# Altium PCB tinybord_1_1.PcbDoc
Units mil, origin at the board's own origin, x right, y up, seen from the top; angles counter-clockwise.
Board outline 1400 x 1800 mil, 2 copper layers (Top Layer, Bottom Layer), stack 21 mil thick; 59 components, 54 nets, 273 pads, 164 vias.
Unrouted connection lines stored in the file: 122.
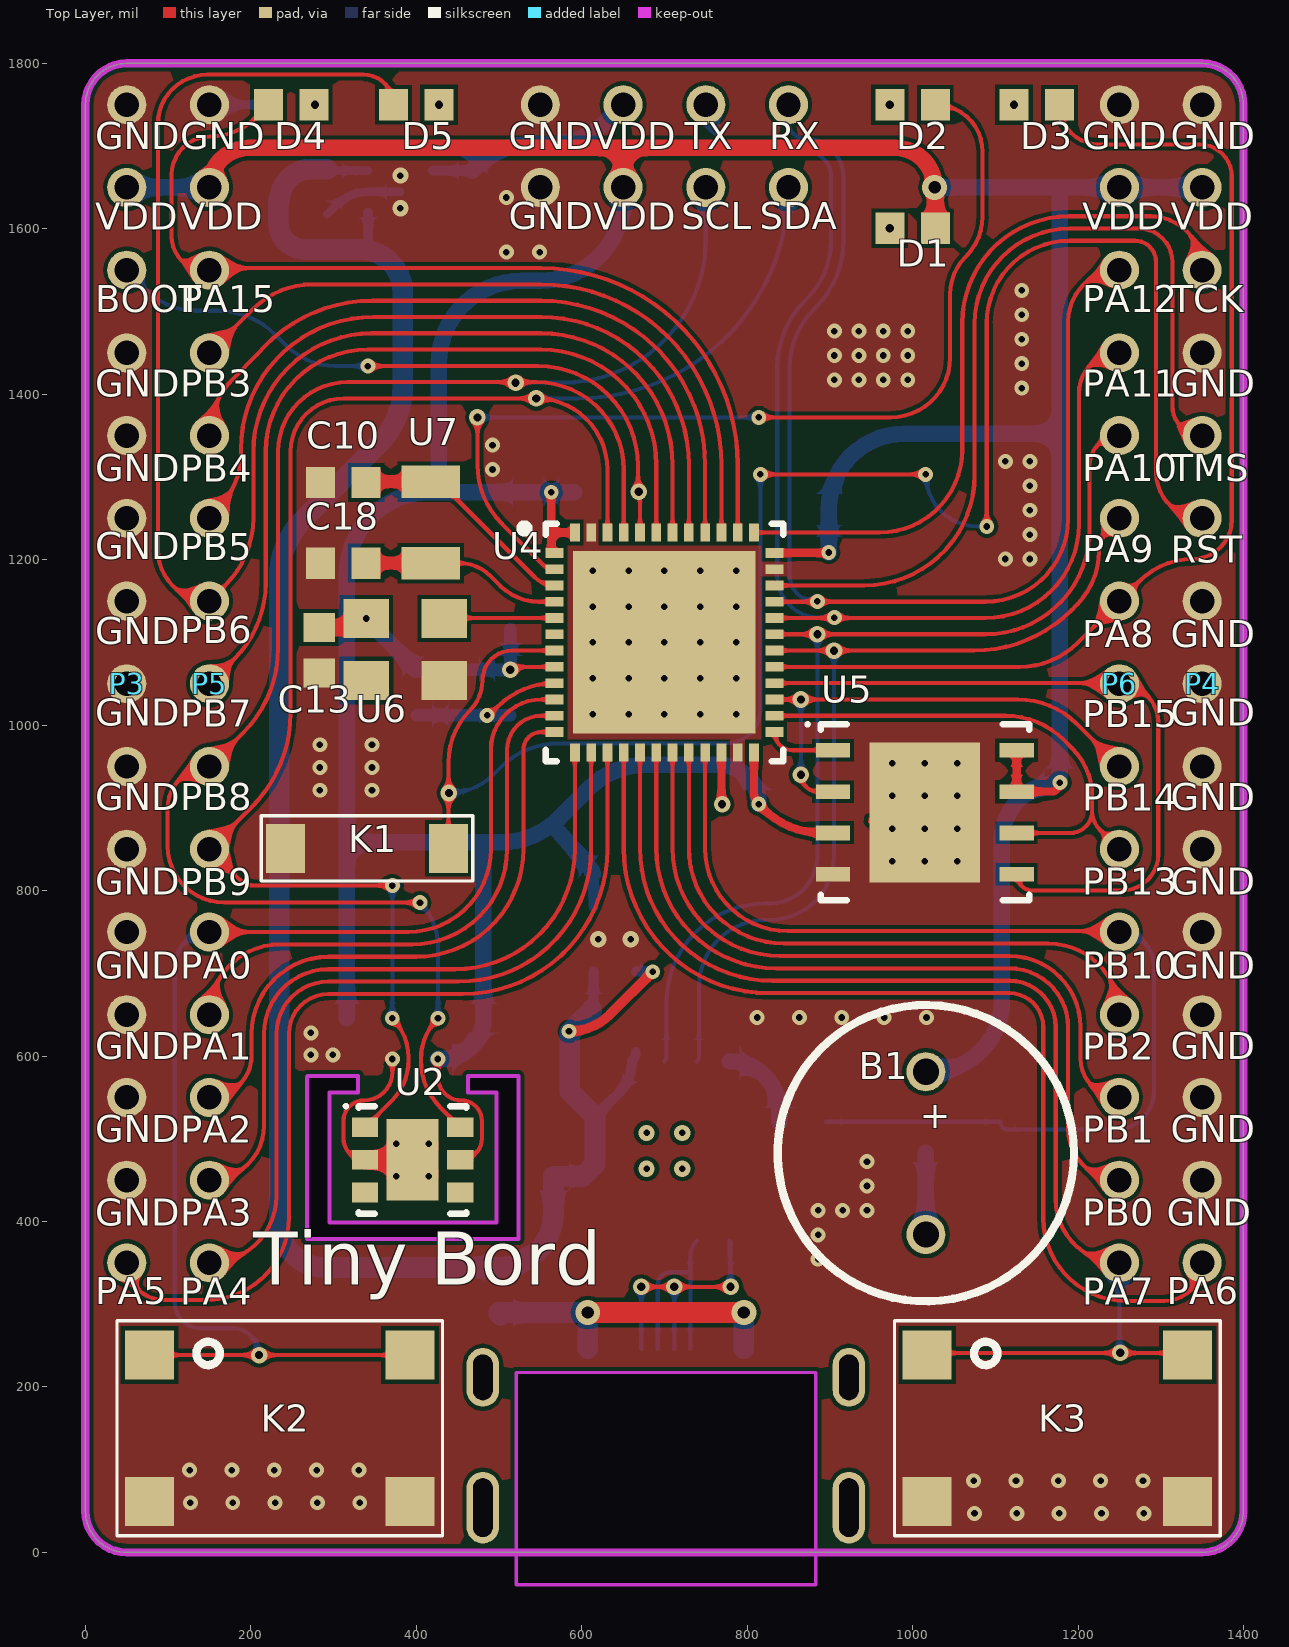
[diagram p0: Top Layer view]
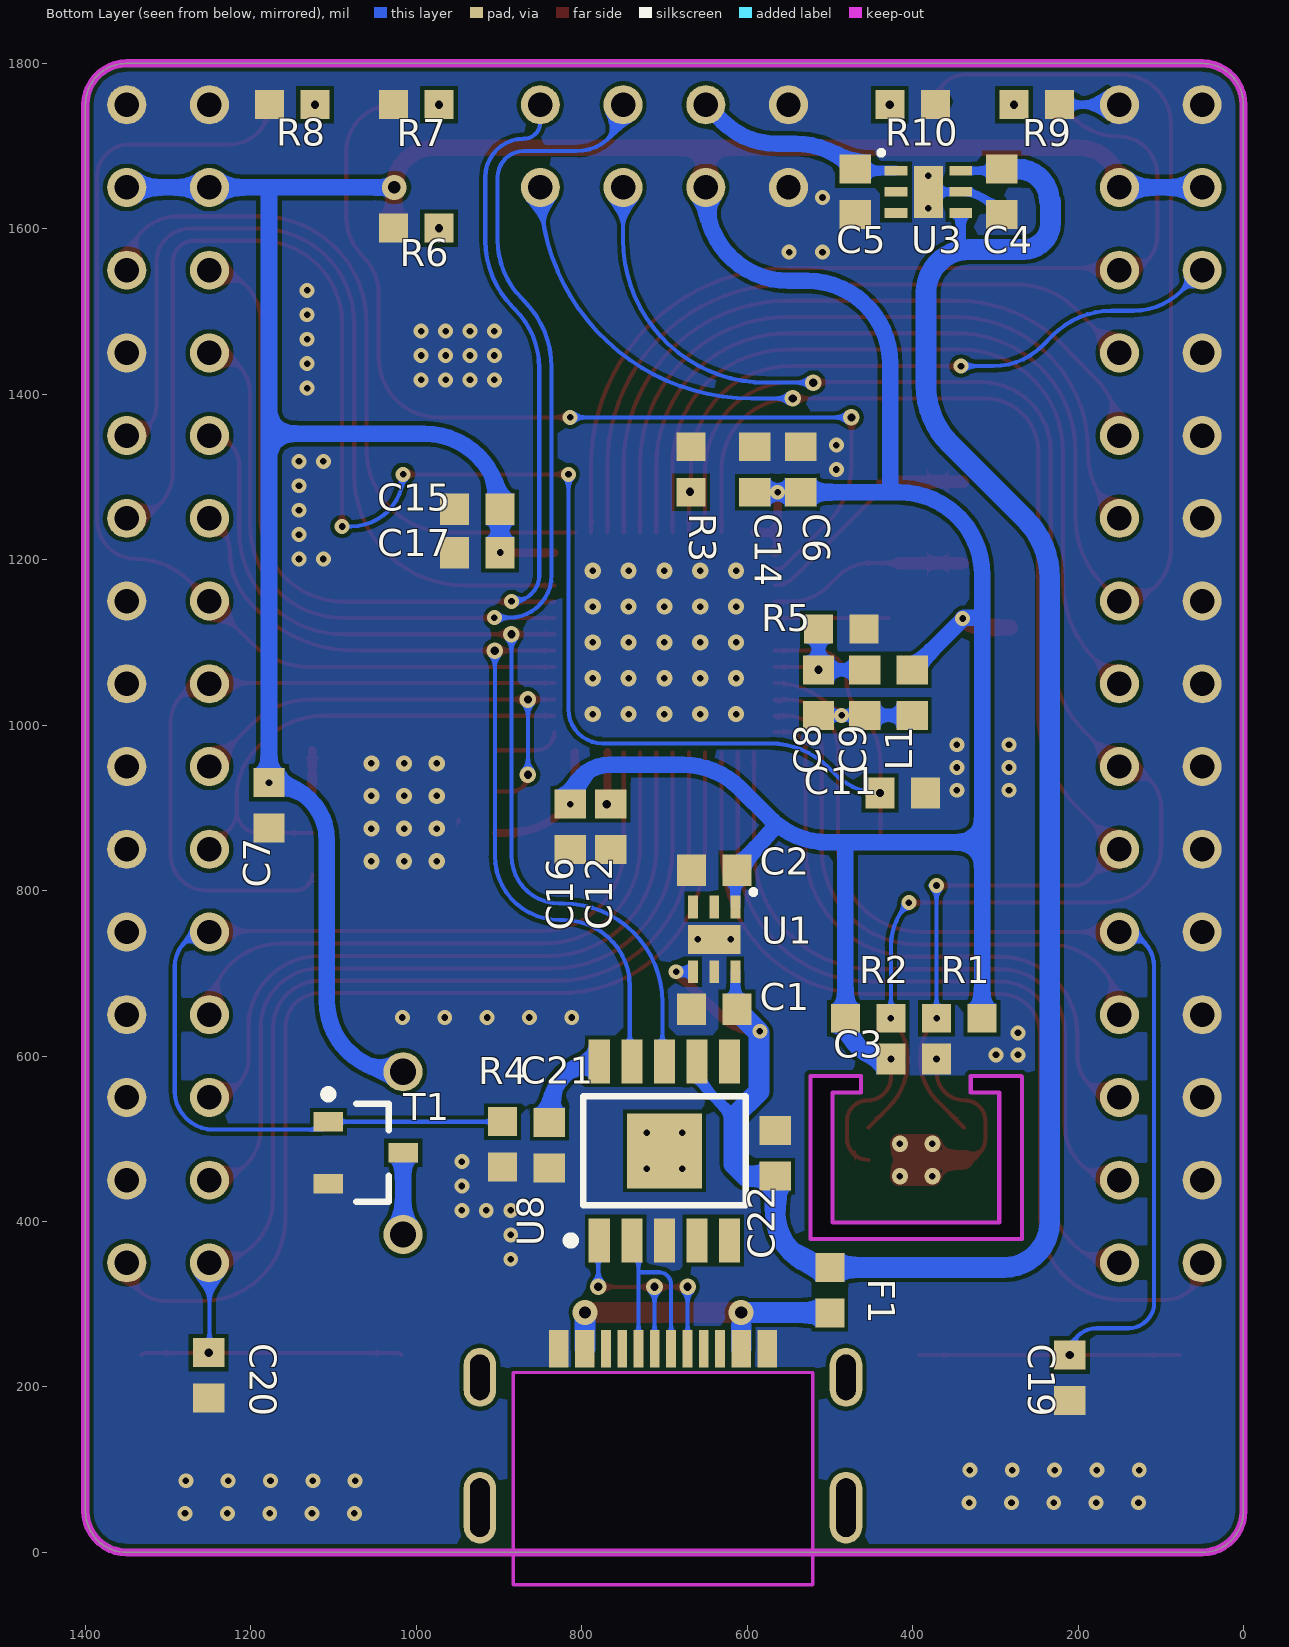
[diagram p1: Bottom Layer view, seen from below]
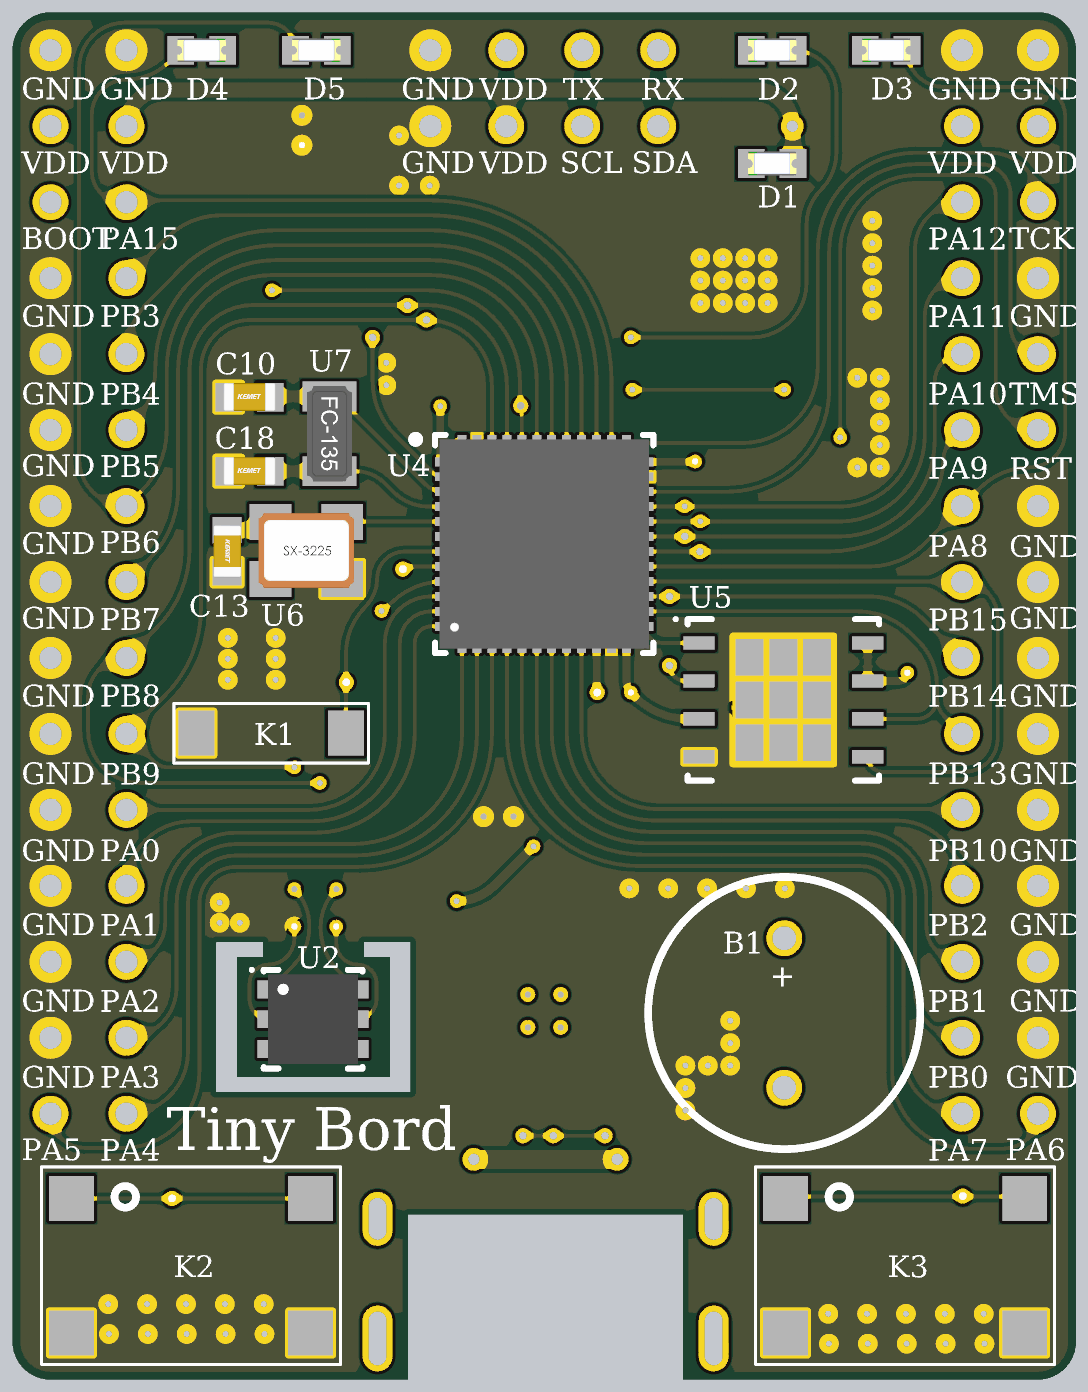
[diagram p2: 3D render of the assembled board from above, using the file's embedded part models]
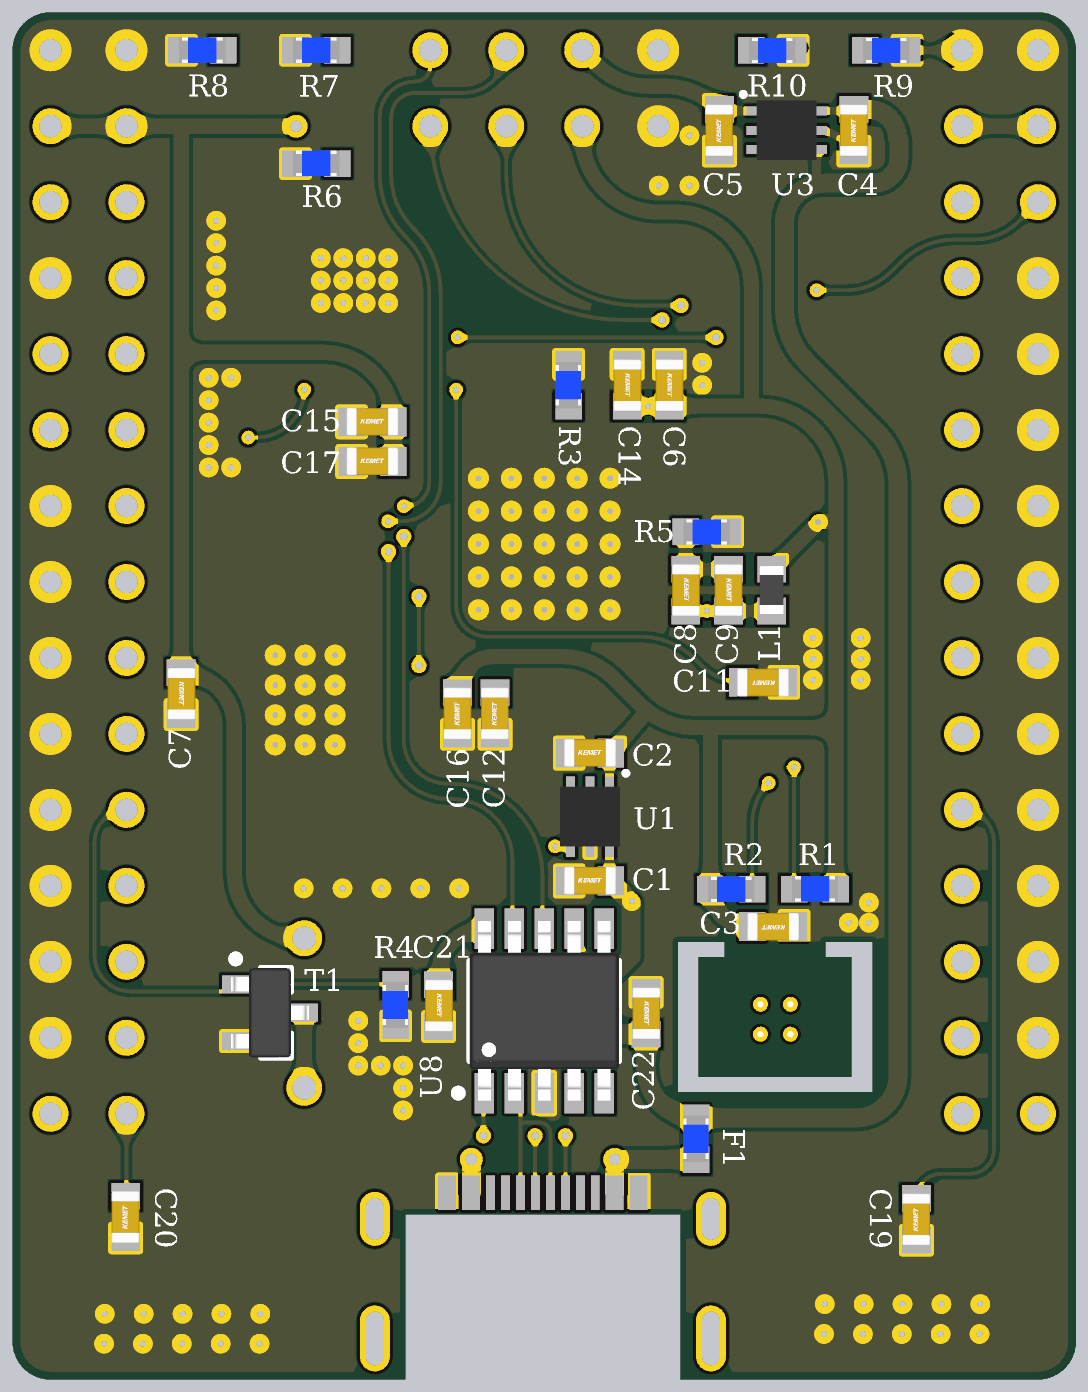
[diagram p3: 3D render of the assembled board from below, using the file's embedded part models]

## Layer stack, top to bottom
Top Solder: solder mask 0.4, Solder Resist, Dk 3.5
Top Layer: signal copper 1.4
Dielectric 2: prepreg 2.8, PP-006, Dk 4.1
Dielectric 1: dielectric 12.6, FR-4, Dk 4.8
Dielectric 3: prepreg 2.8, PP-006, Dk 4.1
Bottom Layer: signal copper 1.4
Bottom Solder: solder mask 0.4, Solder Resist, Dk 3.5

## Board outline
50,0 cw(c50,50) 0,50 0,1750 cw(c50,1750) 50,1800 1350,1800 cw(c1350,1750) 1400,1750 1400,50 cw(c1350,50) 1350,0
cut-out: 267.72,378.94 267.72,574.8 268.7,575.79 329.72,575.79 329.72,556.1 295.28,556.1 295.28,398.62 497.05,398.62 497.05,556.1 462.6,556.1 462.6,575.79 523.62,575.79 523.62,378.94

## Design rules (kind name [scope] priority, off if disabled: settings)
Clearance Clearance_2 [InNamedPolygon('GND_L01_P000')] p1: gap=5 ignorepadtopadclearanceinfootprint=FALSE except(0: Arc-Hole Track-Hole SMDPad-Hole THPad-Hole Via-Hole Fill-Hole Poly-Hole Region-Hole Text-Hole)
Clearance Clearance_1 [InNamedPolygon('Bottom Layer-GND')] p2: gap=5 ignorepadtopadclearanceinfootprint=FALSE except(0: Arc-Hole Track-Hole SMDPad-Hole THPad-Hole Via-Hole Fill-Hole Poly-Hole Region-Hole Text-Hole)
Clearance [All] p3: gap=5 ignorepadtopadclearanceinfootprint=TRUE except(0: Arc-Text Arc-Hole Track-Text Track-Hole SMDPad-Hole THPad-Hole Via-Hole Fill-Hole Poly-Hole Region-Hole Text-Text Text-Hole; 4: Arc-SMDPad Track-SMDPad)
HoleToHoleClearance [All] p1: gap=5 allowstackedmicrovias=TRUE
MinimumSolderMaskSliver [All] p1: minsoldermaskwidth=0
PlaneClearance [All] p1: clearance=11.81
PlaneConnect [All] p1: planeconnectstyle=Direct reliefexpansion=20 reliefentries=4 reliefconductorwidth=10 reliefairgap=10
PolygonConnect PolygonConnect_11 [All vs IsNamedPolygon('GND_L01_P000')] p1: connectstyle=Direct reliefconductorwidth=10 reliefentries=4 polygonreliefangle="90 Angle" airgapwidth=10
PolygonConnect PolygonConnect_10 [All vs IsNamedPolygon('Bottom Layer-GND')] p2: connectstyle=Direct reliefconductorwidth=10 reliefentries=4 polygonreliefangle="90 Angle" airgapwidth=10
PolygonConnect PolygonConnect_9 [All vs IsNamedPolygon('Bottom Layer-GND')] p3: connectstyle=Direct reliefconductorwidth=10 reliefentries=4 polygonreliefangle="90 Angle" airgapwidth=10
PolygonConnect PolygonConnect_8 [All vs IsNamedPolygon('GND_L01_P000')] p4: connectstyle=Direct reliefconductorwidth=10 reliefentries=4 polygonreliefangle="90 Angle" airgapwidth=10
PolygonConnect PolygonConnect_7 [All vs IsNamedPolygon('Bottom Layer-GND')] p5: connectstyle=Relief reliefconductorwidth=10 reliefentries=4 polygonreliefangle="90 Angle" airgapwidth=5
PolygonConnect PolygonConnect_6 [All vs IsNamedPolygon('GND_L01_P000')] p6: connectstyle=Relief reliefconductorwidth=5 reliefentries=4 polygonreliefangle="90 Angle" airgapwidth=5
PolygonConnect PolygonConnect_5 [All vs IsNamedPolygon('GND_L01_P000')] p7: connectstyle=Relief reliefconductorwidth=10 reliefentries=4 polygonreliefangle="90 Angle" airgapwidth=5
PolygonConnect PolygonConnect_4 [All vs IsNamedPolygon('Bottom Layer-GND')] p8: connectstyle=Relief reliefconductorwidth=10 reliefentries=4 polygonreliefangle="90 Angle" airgapwidth=5
PolygonConnect PolygonConnect_3 [All vs IsNamedPolygon('Bottom Layer-GND')] p9: thpad.connectstyle=Relief thpad.reliefconductorwidth=10 thpad.reliefentries=4 thpad.polygonreliefangle="90 Angle" thpad.airgapwidth=5 smdpad.connectstyle=Relief smdpad.reliefconductorwidth=10 smdpad.reliefentries=4 smdpad.polygonreliefangle="90 Angle" smdpad.airgapwidth=10 via.connectstyle=Relief via.reliefconductorwidth=10 via.reliefentries=4 via.polygonreliefangle="90 Angle" via.airgapwidth=10
PolygonConnect PolygonConnect_2 [All vs IsNamedPolygon('Bottom Layer-GND')] p10: thpad.connectstyle=Relief thpad.reliefconductorwidth=10 thpad.reliefentries=4 thpad.polygonreliefangle="90 Angle" thpad.airgapwidth=5 smdpad.connectstyle=Relief smdpad.reliefconductorwidth=10 smdpad.reliefentries=4 smdpad.polygonreliefangle="90 Angle" smdpad.airgapwidth=5 via.connectstyle=Relief via.reliefconductorwidth=10 via.reliefentries=4 via.polygonreliefangle="90 Angle" via.airgapwidth=10
PolygonConnect PolygonConnect_1 [All vs IsNamedPolygon('Bottom Layer-GND')] p11: thpad.connectstyle=Relief thpad.reliefconductorwidth=10 thpad.reliefentries=4 thpad.polygonreliefangle="90 Angle" thpad.airgapwidth=5 smdpad.connectstyle=Relief smdpad.reliefconductorwidth=10 smdpad.reliefentries=4 smdpad.polygonreliefangle="90 Angle" smdpad.airgapwidth=10 via.connectstyle=Relief via.reliefconductorwidth=10 via.reliefentries=4 via.polygonreliefangle="90 Angle" via.airgapwidth=10
PolygonConnect [All] p12: connectstyle=Relief reliefconductorwidth=10 reliefentries=4 polygonreliefangle="90 Angle" airgapwidth=10
RoutingVias [All] p1: holewidth=28 width=50 viastyle="Through Hole" minholewidth=8 minwidth=18 maxholewidth=28 maxwidth=50
ShortCircuit [All] p1: allowed=TRUE
SilkToSilkClearance [All] p1: silktosilkclearance=0
SilkToSolderMaskClearance [IsPad] p1: minsilkscreentomaskgap=0 clearancetoexposedcopper=TRUE
SolderMaskExpansion [All] p1: expansion=4
Width [All] p1: maxlimit=50 minlimit=5 preferedwidth=8 minimp=50.000000 maximp=50.000000 favimp=50.000000
23 further rules are at their usual default settings.

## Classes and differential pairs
component class tinybord: B1 C1 C2 C3 C4 C5 C6 C7 C8 C9 C10 C11 C12 C13 C14 C15 C16 C17 C18 C19 C20 C21 C22 D1 D2 D3 D4 D5 F1 K1 K2 K3 L1 R1 R2 R3 R4 R5 R6 R7 R8 R9 R10 T1 U1 U2 U3 U4 U5 U6 U7 U8

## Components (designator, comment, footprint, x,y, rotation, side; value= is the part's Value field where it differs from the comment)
B1 "BEEP" BEEP0905 1016,482.57 r270 top
C1 "C0603" C0603 639.76,656.5 r180 bottom value=1uF/6.3v
C2 "C0603" C0603 639.76,824.8 r180 bottom value=1uF/6.3v
C3 "C0603" C0603 398.62,596.46 r0 bottom value=100nF
C4 "C0603" C0603 292.32,1644.68 r90 bottom value=1uF/6.3v
C5 "C0603" C0603 469.49,1644.68 r90 bottom value=1uF/6.3v
C6 "C0603" C0603 535.43,1309.06 r270 bottom value=100nF
C7 "C0603" C0603 1178,903 r270 bottom value=100nF
C8 "C0603" C0603 513.78,1039.37 r270 bottom value=1uF
C9 "C0603" C0603 457.68,1039.37 r270 bottom value=100nF
C10 "C0603" C0603 312.01,1293.31 r0 top value=7pF
C11 "C0603" C0603 412,918 r0 bottom value=100nF
C12 "C0603" C0603 764.76,876.97 r90 bottom value=4.7uF
C13 "C0603" C0603 282.48,1090.55 r270 top value=100nF
C14 "C0603" C0603 590.81,1309.06 r270 bottom value=100nF
C15 "C0603" C0603 926.18,1260.83 r180 bottom value=100nF
C16 "C0603" C0603 813.98,876.97 r90 bottom value=100nF
C17 "C0603" C0603 926.18,1208.66 r180 bottom value=10uF
C18 "C0603" C0603 312.01,1195.87 r0 top value=7pF
C19 "C0603" C0603 210,211 r90 bottom value=10nF
C20 "C0603" C0603 1251,214 r90 bottom value=10nF
C21 "C0603" C0603 839,492.37 r270 bottom value=100nF
C22 "C0603" C0603 565.94,482.28 r270 bottom value=100nF
D1 "L0603" led0603 1000,1600.75 r0 top
D2 "L0603" led0603 1000,1750 r0 top
D3 "L0603" led0603 1150,1750 r0 top
D4 "L0603" led0603 249,1750 r180 top
D5 "L0603" led0603 400,1750 r180 top
F1 "FUSE" R0603 500,316.93 r90 bottom
K1 "key_3x4x2" "Key 3x4x2" 242,851 r0 top
K2 "key_6x6" "Key 6x6" 235,150 r0 top locked
K3 "key_6x6" "Key 6x6" 1175,150 r0 top locked
L1 "B0603" B0603 400.59,1039.37 r270 bottom value=330ohm
P1 "OLED" "4x1 header" 550,1650 r0 top
P2 "wireless" "4x1 header" 550,1750 r0 top
P3 "m15Pin" "15x1 header" 50,1750 r270 top
P4 "m15Pin" "15x1 header" 1350,1750 r270 top
P5 "m15Pin" "15x1 header" 150,1750 r270 top
P6 "m15Pin" "15x1 header" 1250,1750 r270 top
P7 "USB-Type-c" USB-TYPE-C 701.77,223.43 r180 bottom locked
R1 "R0603" R0603 343.5,645.67 r180 bottom value=10K
R2 "R0603" R0603 453.74,645.67 r0 bottom value=10K
R3 "R0603" R0603 668,1309.06 r90 bottom value=10K
R4 "R0603" R0603 895.67,493.11 r90 bottom value=10K
R5 "R0603" R0603 486.22,1116.14 r0 bottom value=0R
R6 "R0603" R0603 1000,1600.75 r180 bottom value=10K
R7 "R0603" R0603 1000,1750 r180 bottom value=1K
R8 "R0603" R0603 1150,1750 r180 bottom value=1K
R9 "R0603" R0603 250,1750 r0 bottom value=1K
R10 "R0603" R0603 400,1750 r0 bottom value=1K
T1 "NMOS" NMOS-BSH103 1061,483 r180 bottom
U1 "LP5912" LP5912 639.76,741.14 r270 bottom
U2 "SHT21" SHT21 395.67,474.41 r0 top
U3 "LP5912" LP5912 380.91,1644.68 r180 bottom
U4 "STM32F411CE" "STM32F411CE QFN" 700,1100 r0 top
U5 "W25Q128JV_QFN" "W25Q64 QFN" 1014.76,894.68 r0 top
U6 "SG-310SCF" SG-310SCF 386.81,1091.54 r0 top
U7 "FC-135" FC-135 417.32,1245.08 r90 top
U8 "CH9340K" CH9340 700,485.37 r90 bottom

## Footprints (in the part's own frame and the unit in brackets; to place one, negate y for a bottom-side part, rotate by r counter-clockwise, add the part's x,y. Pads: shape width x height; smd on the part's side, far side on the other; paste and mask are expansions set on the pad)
"4x1 header" [mm]
  round 1.2 hole 0.75: 1(0,0) 2(2.54,0) 3(5.08,0) 4(7.62,0)
"15x1 header" [mm]
  round 1.2 hole 0.75: 1(0,0) 2(2.54,0) 3(5.08,0) 4(7.62,0) 5(10.16,0) 6(12.7,0) 7(15.24,0) 8(17.78,0) 9(20.32,0) 10(22.86,0) 11(25.4,0) 12(27.94,0) 13(30.48,0) 14(33.02,0) 15(35.56,0)
B0603 [mil]
  rect 35x38 smd: 1(-27.5,0) 2(27.5,0)
  body extent -31,-16 31,16, height 31
BEEP0905 [mm]
  round 1.2 hole 0.8: 1(-2.5,0) 2(2.5,0)
  silkscreen extent -4.55,-4.55 4.55,4.55
C0603 [mil]
  rect 35x38 smd: 1(-27.5,0) 2(27.5,0)
  body extent -34,-18 34,19, height 33
CH9340 [mm]
  rect 1.35x0.65 smd: 1(-2.75,2) 2(-2.75,1) 3(-2.75,0) 4(-2.75,-1) 5(-2.75,-2) 6(2.75,-2) 7(2.75,-1) 8(2.75,0) 9(2.75,1) 10(2.75,2)
  rect 2.3x2.3 smd: 11(0,0)
  silkscreen extent -2.87,-2.5 1.68,3, body extent -3,-2.5 3,2.5, height 1.8
FC-135 [mm]
  rect 1x1.8 smd: 1(-1.25,0) 2(1.25,0)
  body extent -1.6,-0.75 1.6,0.75, height 0.8
"Key 3x4x2" [mm]
  rect 1.2x1.5 smd: 1(0,0) 2(5,0)
  silkscreen extent -0.75,-1 5.75,1
"Key 6x6" [mm]
  rect 1.5x1.5 smd: 1(-4,2.25) 2(4,2.25) 3(-4,-2.25) 4(4,-2.25)
  silkscreen extent -5,-3.3 5,3.3
led0603 [mil]
  rect 35x38 smd: 1(-27.5,0) 2(27.5,0)
  body extent -32,-16 32,16, height 24
LP5912 [mm] "SON, 6-Leads, Body 2.00x2.00mm, Pitch 0.65mm, Thermal Pad 1.60x0.89mm, IPC Medium Density"
  rect 0.7x0.3 smd: 1(-0.995,0.65) 2(-0.995,0) 3(-0.995,-0.65) 4(0.995,-0.65) 5(0.995,0) 6(0.995,0.65)
  rect 0.89x1.6 smd: 7(0,0)
  silkscreen extent -1.5,1.15 -1.4,1.25, body extent -1,-1 1,1, height 0.8
NMOS-BSH103 [mm] "SOT23, 3-Leads, Body 2.90x2.30mm, Pitch 0.95mm, IPC Medium Density"
  rect 0.9x0.6 smd: 1(-1.15,0.95) 2(-1.15,-0.95) 3(1.15,0)
  silkscreen extent -1.28,-1.5 0.7,1.92, body extent -1.3,-1.5 1.3,1.5, height 1.1
R0603 [mil]
  rect 35x35 smd: 1(-27.5,0) 2(27.5,0)
  body extent -31,-16 31,17, height 18
SG-310SCF [mm] "3225"
  rect 1.4x1.2 smd: 1(-1.2,-0.95) 2(1.2,-0.95) 3(1.2,0.95) 4(-1.2,0.95)
  body extent -1.6,-1.25 1.6,1.25, height 0.81
SHT21 [mm] "SON, 6-Leads, Body 3.00x3.00mm, Pitch 1.00mm, Thermal Pad 2.40x1.50mm, IPC Medium Density"
  rect 0.8x0.6 smd: 1(-1.46,1) 2(-1.46,0) 3(-1.46,-1) 4(1.46,-1) 5(1.46,0) 6(1.46,1)
  rect 1.6x2.5 smd paste-0.75: 7(0,0)
  silkscreen extent -2.1,-1.65 1.65,1.7, body extent -1.5,-1.5 1.5,1.5, height 1.1
"STM32F411CE QFN" [mm] "QFN, 48-Leads, Body 7.00x7.00mm, Pitch 0.50mm, Thermal Pad 5.60x5.60mm, IPC Medium Density"
  rect 0.55x0.3 smd: 1(-3.375,2.75) 2(-3.375,2.25) 3(-3.375,1.75) 4(-3.375,1.25) 5(-3.375,0.75) 6(-3.375,0.25) 7(-3.375,-0.25) 8(-3.375,-0.75) 9(-3.375,-1.25) 10(-3.375,-1.75) 11(-3.375,-2.25) 12(-3.375,-2.75) 25(3.375,-2.75) 26(3.375,-2.25) 27(3.375,-1.75) 28(3.375,-1.25) 29(3.375,-0.75) 30(3.375,-0.25) 31(3.375,0.25) 32(3.375,0.75) 33(3.375,1.25) 34(3.375,1.75) 35(3.375,2.25) 36(3.375,2.75)
  rect 0.3x0.55 smd: 13(-2.75,-3.375) 14(-2.25,-3.375) 15(-1.75,-3.375) 16(-1.25,-3.375) 17(-0.75,-3.375) 18(-0.25,-3.375) 19(0.25,-3.375) 20(0.75,-3.375) 21(1.25,-3.375) 22(1.75,-3.375) 23(2.25,-3.375) 24(2.75,-3.375) 37(2.75,3.375) 38(2.25,3.375) 39(1.75,3.375) 40(1.25,3.375) 41(0.75,3.375) 42(0.25,3.375) 43(-0.25,3.375) 44(-0.75,3.375) 45(-1.25,3.375) 46(-1.75,3.375) 47(-2.25,3.375) 48(-2.75,3.375)
  rect 5.6x5.6 smd: 49(0,0)
  silkscreen extent -4.42,-3.65 3.65,3.65, body extent -3.5,-3.5 3.5,3.5, height 0.55
USB-TYPE-C [mm]
  rect 0.6x1.15 smd: 1(-3.2,0.575) 2(-2.4,0.575) 11(2.4,0.575) 12(3.2,0.575)
  rect 0.3x1.15 smd: 3(-1.75,0.575) 4(-1.25,0.575) 5(-0.75,0.575) 6(-0.25,0.575) 7(0.25,0.575) 8(0.75,0.575) 9(1.25,0.575) 10(1.75,0.575)
  rrect100% 1x1.8 hole 1.4 slot 0.6 at 0 deg: 13(-5.62,-0.3) 15(5.62,-0.3)
  rrect100% 1x2.2 hole 1.8 slot 0.6 at 0 deg: 14(-5.62,-4.3) 16(5.62,-4.3)
  Keep-Out Layer board cut-out: -4.6,-6.665 -4.6,-0.152 4.6,-0.152 4.6,-6.665
  Keep-Out Layer lines w0.1: 4.597,-6.665 -4.597,-6.665 -4.597,-0.152 4.597,-0.152 4.597,-6.665
"W25Q64 QFN" [mm]
  rect 1.05x0.45 smd: 1(-2.82,1.905) 2(-2.82,0.635) 3(-2.82,-0.635) 4(-2.82,-1.905) 5(2.82,-1.905) 6(2.82,-0.635) 7(2.82,0.635) 8(2.82,1.905)
  rect 3.4x4.3 smd paste-1.7: 9(0,0)
  silkscreen extent -3.65,-2.7 3.2,2.75, body extent -3.05,-2.55 3.05,2.55, height 0.8

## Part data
B1: "12*6"
C1 C2 C3 C4 C5 C6 C7 C8 C9 C10 C11 C12 C13 C14 C15 C16 C17 C18 C19 C20 C21 C22: "陶瓷电容"
D1 D2 D3 D4 D5: "LED"
F1: library part PTC0603, "PTC 1812"
K1 K2 K3: "贴片按键"
L1: "磁珠"
P1 P2: library part m4Pin, "1x4pin 1.27mm"
P3 P4 P5 P6: "1x4pin 1.27mm"
P7: "use typec 16p"
R1 R2 R3 R4 R5 R6 R7 R8 R9 R10: "电阻"
T1: library part NMOS-BSH103, "infineon P-Chanel"
U1 U3: "LDO"
U2: "温湿度传感器"
U4: "STM32F411 QFN48PIN"
U5: "flash"
U6: "有源晶振3225"
U7: "32.768K无源晶振"
U8: "USB转串口"

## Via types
v1: diameter 18, hole 8, Top Layer to Bottom Layer, 91 vias
v2: diameter 19.68, hole 7.87, Top Layer to Bottom Layer, 49 vias
v3: diameter 20, hole 10, Top Layer to Bottom Layer, 21 vias
v4: diameter 30, hole 15, Top Layer to Bottom Layer, 3 vias

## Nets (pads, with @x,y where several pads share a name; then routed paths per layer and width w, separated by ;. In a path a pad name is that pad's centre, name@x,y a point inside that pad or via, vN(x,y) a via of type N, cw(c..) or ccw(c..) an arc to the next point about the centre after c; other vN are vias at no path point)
BOOT: P3.3 R3.1 U4.44 | length 809.3
  Top Layer w5: v1(341.54,1434.06) 547.28,1434.06 cw(c547.28,1313.29) 668.04,1313.29 668.04,1282.96 ccw(c669,1282.96) v3(669,1282) 665.8,1282 665.35,1281.56 cw(c653,1269.2) 670.47,1269.2 U4.44
  Bottom Layer w5: P3.3 75.1,1524.9 ccw(c132.87,1582.73) 132.87,1500.98 159.37,1500.98 cw(c159.37,1400.98) 230.08,1471.69 243.11,1458.66 ccw(c302.52,1518.07) 302.52,1434.06 v1(341.54,1434.06)
GND: C1.1 C2.1 C3.1 C4.1 C5.1 C6.1 C7.2 C10.1 C11.1 C12.1 C13.2 C14.1 C15.1 C16.1 C17.1 C18.1 C19.1 C20.1 C21.2 C22.1 K1.1 K2.3 K2.4 K3.3 K3.4 P1.1 P2.1 P3.1 P3.4 P3.5 P3.6 P3.7 P3.8 P3.9 P3.10 P3.11 P3.12 P3.13 P3.14 P4.1 P4.4 P4.7 P4.8 P4.9 P4.10 P4.11 P4.12 P4.13 P4.14 P5.1 P6.1 P7.1 P7.12 R3.2 R4.1 R5.1 R6.1 R7.1 R8.1 R9.1 R10.1 T1.2 U1.5 U1.7 U2.2 U2.7 U3.5 U3.7 U4.23 U4.35 U4.47 U4.49 U5.4 U5.9 U6.2 U8.3 | length 633.3
  Top Layer w5: U2.2 cw(c338.19,500.59) 312.01,500.59 312.01,521.65 cw(c336.61,521.65) 336.61,546.26 ccw(c336.61,580.77) 371.12,580.77 v1(371.12,596.46)
  Top Layer w23.62: U2.2 U2.7 cw(c395.67,454.72) U2.7@407.48,470.47 ; U2.7@407.48,470.47 ccw(c375.98,494.09) U2.7@410.08,474.41 ; U2.7@407.48,470.47 cw(c375.98,494.09) v2(375.98,454.72) v2(415.35,454.72) ; U2.7@407.48,470.47 cw(c395.67,454.72) v2(415.35,454.72) ; U2.7@410.08,474.41 ccw(c375.98,494.09) v2(415.35,494.09) v2(375.98,494.09) cw(c375.98,454.72) U2.7@410.08,474.41 ; U2.7@410.08,474.41 cw(c375.98,454.72) v2(415.35,454.72)
  Bottom Layer w10: P5.1 R9.1 ; C4.1 304.33,1629.19 cw(c341.73,1591.79) U3.5 U3.7 ; R10.1@361.81,1754 cw(c361.81,1753.02) R10.1@362.8,1753.02
  other v1: 1074.8,47.24 1125.98,47.24 1177.17,47.24 1228.35,47.24 1279.53,47.24 126.97,60.04 178.15,60.04 229.33,60.04 280.51,60.04 331.69,60.04 1073.82,86.61 1125,86.61 1176.18,86.61 1227.36,86.61 1278.54,86.61 125.98,99.41 177.17,99.41 228.35,99.41 279.53,99.41 330.71,99.41 885.83,354.33 885.83,383.86 885.83,413.39 915.35,413.39 944.88,413.39 944.88,442.91 944.88,472.44 272.64,601.38 299.21,601.38 272.64,627.95 812.01,646.65 863.19,646.65 914.37,646.65 965.55,646.65 1016.73,646.65 283.46,921.26 346.46,921.26 283.46,948.82 346.46,948.82 283.46,976.38 346.46,976.38 1112.2,1200.79 1141.73,1200.79 1141.73,1230.32 1141.73,1259.84 1141.73,1289.37 492.13,1309.06 1112.2,1318.9 1141.73,1318.9 492.13,1338.58 1131.89,1407.48 905.51,1417.32 935.04,1417.32 964.57,1417.32 994.09,1417.32 1131.89,1437.01 905.51,1446.85 935.04,1446.85 964.57,1446.85 994.09,1446.85 1131.89,1466.54 905.51,1476.38 935.04,1476.38 964.57,1476.38 994.09,1476.38 1131.89,1496.06 1131.89,1525.59 508.86,1571.85 549.21,1571.85 508.86,1637.8
  other v2: 620.08,741.14 659.45,741.14 975.39,835.63 1014.76,835.63 1054.13,835.63 975.39,875 1014.76,875 1054.13,875 975.39,914.37 1014.76,914.37 1054.13,914.37 975.39,953.74 1014.76,953.74 1054.13,953.74 613.39,1013.39 656.69,1013.39 700,1013.39 743.31,1013.39 786.61,1013.39 613.39,1056.69 656.69,1056.69 700,1056.69 743.31,1056.69 786.61,1056.69 613.39,1100 656.69,1100 700,1100 743.31,1100 786.61,1100 613.39,1143.31 656.69,1143.31 700,1143.31 743.31,1143.31 786.61,1143.31 613.39,1186.61 656.69,1186.61 700,1186.61 743.31,1186.61 786.61,1186.61 380.91,1625 380.91,1664.37
NetB1_2: B1.2 T1.3 | length 99.1
  Bottom Layer w20: T1.3 1016,483 B1.2
NetC8_1: C8.1 C9.1 R5.2 U4.8 | length 160.8
  Top Layer w5: v3(513.78,1066.87) cw(c517.38,1066.87) 517.38,1070.47 U4.8
  Bottom Layer w15: C9.1 v3(513.78,1066.87) ; R5.2 v3(513.78,1066.87) ; v3(513.78,1066.87) v3(513.78,1066.87)
NetC8_2: C8.2 C9.2 L1.2 U4.9 | length 204.3
  Top Layer w5: v1@487.99,1011.87 498.46,1022.34 cw(c567.13,953.68) U4.9
  Bottom Layer w15: L1.2 C9.2 v1(485.73,1011.87) C8.2
NetC12_2: C12.2 U4.22 | length 62.8
  Top Layer w10: U4.22 768.9,906.43 ccw(c771.59,906.43) v3(769.68,904.53)
NetC21_1: C21.1 U8.10 | length 108.2
  Bottom Layer w20: U8.10 cw(c778.74,533.38) 839,533.38 C21.1
NetD1_1: D1.1 R6.2
  other v3: 972.5,1600.75
NetD2_1: D2.1 R7.2
  other v3: 972.5,1750
NetD3_1: D3.1 R8.2
  other v3: 1122.5,1750
NetD4_1: D4.1 R9.2
  other v3: 277.5,1750
NetD5_1: D5.1 R10.2
  other v3: 427.5,1750
NRST: C11.2 K1.2 P4.6 U4.7 | length 2213.7
  Top Layer w5: K1.2@449.85,862 ccw(c449.85,851) K1.2 438.85,954.87 cw(c528.13,954.87) 465,1018 ccw(c428.79,1054.21) 480,1054.21 cw(c515.94,1054.21) 515.94,1090.16 U4.7 ; v1(815.99,1303.2) v1(1015.8,1303.2) ; v1@1089.57,1240.2 1089.57,1485.63 cw(c1189.57,1485.63) 1189.57,1585.63 1268.7,1585.63 cw(c1268.7,1560.04) 1294.29,1560.04 1294.29,1305.71 ccw(c1350,1305.71) P4.6
  Bottom Layer w5: v3(439.5,918) ccw(c439.5,994.05) 493.27,940.27 501.71,948.71 cw(c572.42,878) 572.42,978 775.07,978 ccw(c775.07,1018.88) 815.94,1018.88 v1(815.99,1303.2) ; v1(1015.8,1303.2) ccw(c1078.79,1303.2) 1078.79,1240.2 v1(1089.61,1240.2)
OSC32_IN: C10.2 U4.3 U7.2 | length 302.2
  Top Layer w5: U7.2@441.93,1294.29 U7.2 cw(c417.32,1269.22) 435.05,1286.95 543.2,1178.8 ccw(c567.13,1202.75) U4.3
  Top Layer w15: C10.2 cw(c340.49,1293.31) 340.49,1294.29 U7.2
OSC32_OUT: C18.2 U4.4 U7.1 | length 241.8
  Top Layer w5: U7.1 452.29,1195.87 cw(c452.29,1143.14) 489.58,1180.42 501.41,1168.59 ccw(c548.19,1215.36) 548.19,1149.21 U4.4
  Top Layer w15: C18.2 U7.1
OSC_IN: U4.5 U6.3 | length 139.6
  Top Layer w5: U6.3@429.13,1128.94 429.13,1129.53 U4.5@568.11,1129.53
PA0: C19.2 K2.1 K2.2 P5.11 U4.10 | length 1562.7
  Top Layer w5: K2.1 v3(210,238.5) v3(210,238.5) K2.2 K2.2 ; P5.11 390.16,750 ccw(c390.16,850) 490.16,850 490.16,970.08 cw(c551.18,970.08) 551.18,1031.1 U4.10 cw(c561.09,1037.14) 561.09,1028.6 U4.10@559.6,1028.6
  Bottom Layer w5: P5.11 ccw(c150,708) 108,708 108,302 ccw(c139,302) 139,271 177.5,271 cw(c177.5,238.5) v3(210,238.5)
PA1: P5.12 U4.11 | length 681.7
  Top Layer w5: P5.12 cw(c235,650) 235,735 394.84,735 ccw(c394.84,850) 509.84,850 509.84,970.08 cw(c551.18,970.08) 551.18,1011.42 U4.11 cw(c561.09,1017.45) U4.11@561.09,1008.92
PA4: P5.15 U4.14 | length 948.1
  Top Layer w5: P5.15 ccw(c150,431) 231,431 231,627 cw(c294,627) 294,690 451.42,690 ccw(c451.42,850) 611.42,850 U4.14
PA5: P3.15 U4.15 | length 1130.3
  Top Layer w5: P3.15 ccw(c95,350) 95,305 146,305 ccw(c146,405) 246,405 246,627 cw(c294,627) 294,675 456.1,675 ccw(c456.1,850) 631.1,850 U4.15
PA6: P4.15 U4.16 | length 1253
  Top Layer w5: U4.16 650.79,851 ccw(c825.79,851) 825.79,676 1117,676 cw(c1117,635) 1158,635 1158,404 ccw(c1258,404) 1258,304 1304,304 ccw(c1304,350) P4.15
PA7: C20.2 K3.1 K3.2 P6.15 U4.17 | length 1496.8
  Top Layer w5: U4.17 670.47,851 ccw(c830.47,851) 830.47,691 1117,691 cw(c1117,635) 1173,635 1173,427 ccw(c1250,427) P6.15 ; K3.1 cw(c1023.36,232.75) 1023.36,241 1326.64,241 cw(c1326.64,232.75) K3.2
  Bottom Layer w5: P6.15 1250,243.5 ccw(c1252,243.5) C20.2@1252,241.5
  other v3: 1251,241.5
PA8: D3.2 P6.7 U4.29 | length 1298.8
  Top Layer w5: U4.29 1129.05,1070.47 ccw(c1129.05,1170.47) 1199.76,1099.76 P6.7 1274.06,1174.06 cw(c1338.58,1109.54) 1338.58,1200.79 ccw(c1338.58,1248.03) 1385.83,1248.03 1385.83,1663.39 ccw(c1347.44,1663.39) 1347.44,1701.77 1225.73,1701.77 cw(c1225.73,1750) D3.2
PA9: P6.6 U4.30 U8.9 | length 1094.1
  Top Layer w5: U4.30 1074.29,1090.16 ccw(c1074.29,1256.42) 1191.85,1138.85 1198.36,1145.36 ccw(c1133.09,1210.63) 1225.39,1210.63 cw(c1261.04,1210.63) 1235.83,1235.83 P6.6
  Bottom Layer w5: U8.9 ccw(c733.33,599.67) 741.87,599.67 741.87,684.47 cw(c821.85,684.47) 821.85,764.45 827.16,764.45 ccw(c827.16,842.28) 905,842.28 v3(905,1090)
PA10: P6.5 U4.31 U8.8 | length 1211.2
  Top Layer w5: U4.31 1088,1109.84 ccw(c1088,1235.84) 1214,1235.84 1214,1314 cw(c1250,1314) P6.5
  Bottom Layer w5: U8.8 ccw(c693.96,599.67) 702.5,599.67 702.5,665.1 cw(c821.85,665.1) 821.85,784.45 827.16,784.45 ccw(c827.16,842.28) 885,842.28 v3(885,1110)
PA11: P2.3 P6.4 U4.32 | length 1467
  Top Layer w5: U4.32 1088,1129.53 ccw(c1088,1242.53) 1201,1242.53 1201,1401 cw(c1250,1401) P6.4
  Bottom Layer w5: P2.3 ccw(c806.1,1750) 806.1,1693.9 870.08,1693.9 cw(c870.08,1662.4) 901.57,1662.4 901.57,1586.26 cw(c801.57,1586.26) 872.29,1515.55 870.06,1513.32 ccw(c951.38,1432) 836.38,1432 836.38,1181.1 ccw(c887.56,1181.1) 887.56,1129.92 v1(905.51,1129.92)
PA12: P2.4 P6.3 U4.33 | length 1424.5
  Top Layer w5: U4.33 1088,1149.21 ccw(c1088,1249.21) 1188,1249.21 1188,1488 cw(c1250,1488) P6.3
  Bottom Layer w5: P2.4 850,1728.98 ccw(c870.08,1728.98) 870.08,1708.9 cw(c870.08,1662.4) 916.57,1662.4 916.57,1586.26 cw(c801.57,1586.26) 882.89,1504.94 880.67,1502.71 ccw(c951.38,1432) 851.38,1432 851.38,1181.1 ccw(c882.87,1181.1) 882.87,1149.61 v1(884.84,1149.61)
PA15: D4.2 P5.3 U4.38 | length 1157.8
  Top Layer w5: D4.2 206.11,1734.61 cw(c150.59,1790.13) 150.59,1711.61 ccw(c150.59,1665.35) 104.33,1665.35 104.33,1590.55 ccw(c144.88,1590.55) 144.88,1550 P5.3 cw(c152.48,1550) 152.48,1552.48 550.79,1552.48 cw(c550.79,1314.69) 788.58,1314.69 U4.38 ; D4.2@222.5,1750 D4.2@223,1750
PB0: P6.14 U4.18 | length 957.6
  Top Layer w5: U4.18 690.16,851 ccw(c835.16,851) 835.16,706 1117,706 cw(c1117,635) 1188,635 1188,512 ccw(c1250,512) P6.14
PB1: P6.13 U4.19 | length 844.4
  Top Layer w5: U4.19 709.84,851 ccw(c839.84,851) 839.84,721 1117,721 cw(c1117,635) 1203,635 1203,597 ccw(c1250,597) P6.13
PB2: P6.12 U4.20 | length 742.3
  Top Layer w5: U4.20 729.53,851 ccw(c844.53,851) 844.53,736 1164,736 cw(c1164,650) P6.12@1249.42,660 ; P6.12@1249,650 P6.12
PB3: P5.4 U4.39 | length 855.2
  Top Layer w5: P5.4 203.51,1503.51 cw(c274.22,1432.8) 274.22,1532.8 550.79,1532.8 cw(c550.79,1314.69) 768.9,1314.69 U4.39
PB4: P5.5 U4.40 | length 873.7
  Top Layer w5: P5.5 cw(c247.14,1350) 178.42,1418.66 208.18,1448.42 cw(c346.92,1332) 346.92,1513.11 550.79,1513.11 cw(c550.79,1314.69) 749.21,1314.69 U4.40
PB5: P5.6 U4.41 | length 911.5
  Top Layer w5: P5.6 158.74,1258.74 ccw(c88.03,1329.45) 188.03,1329.45 188.03,1333.43 cw(c348.03,1333.43) 348.03,1493.43 550.79,1493.43 cw(c550.79,1314.69) 729.53,1314.69 U4.41
PB6: D5.2 P5.7 U4.42 | length 1910.7
  Top Layer w5: D5.2 ccw(c336.08,1750) 336.08,1786.42 147.64,1786.42 ccw(c147.64,1726.38) 87.6,1726.38 87.6,1212.4 ccw(c150,1212.4) P5.7 169.35,1169.35 ccw(c88.03,1250.67) 203.03,1250.67 203.03,1330.71 cw(c346.06,1330.71) 346.06,1473.74 550.79,1473.74 cw(c550.79,1314.69) 709.84,1314.69 U4.42
PB7: P5.8 U4.43 | length 1007.2
  Top Layer w5: P5.8 179.96,1079.96 ccw(c88.03,1171.88) 218.03,1171.88 218.03,1330.71 cw(c341.38,1330.71) 341.38,1454.06 545,1454.06 550.79,1454.06 cw(c550.79,1314.69) 690.16,1314.69 U4.43
PB8: P1.3 P5.9 R2.1 U2.6 U4.45 | length 2171.5
  Top Layer w5: v1(404.53,785.43) 168.29,785.43 cw(c168.29,854.31) 99.41,854.31 99.41,899.41 cw(c150,899.41) P5.9 190.56,990.56 ccw(c88.03,1093.09) 233.03,1093.09 233.03,1330.71 cw(c317.01,1330.71) 317.01,1414.68 545.1,1414.68 cw(c545.1,1309) 650.79,1309 U4.45 ; v1(426.24,645.67) ccw(c476.28,595.63) 405.51,595.63 405.51,595.47 ccw(c487.73,595.47) 429.59,537.34 U2.6
  Bottom Layer w5: v1(426.24,645.67) 426.24,733.01 ccw(c352.11,733.01) v1@404.82,785.13 ; v3(520,1414) 577.23,1414 ccw(c577.23,1586.77) 750,1586.77 P1.3 ; v1@404.82,785.13 ccw(c352.11,733.01) v1(404.53,785.43) v1@404.82,785.14
PB9: P1.4 P5.10 R1.1 U2.1 U4.46 | length 2072.4
  Top Layer w5: U2.1 370.15,545.74 ccw(c320.41,595.47) 390.75,595.47 390.75,598 ccw(c323.34,598) v1(371,645.67) ; v1(371.06,806.1) 203.74,806.1 cw(c203.74,829.86) 186.94,813.06 P5.10 201.17,901.17 ccw(c88.03,1014.31) 248.03,1014.31 248.03,1330.71 cw(c312.32,1330.71) 312.32,1395 v3(545,1395) 545.1,1395 cw(c545.1,1309) 631.1,1309 U4.46
  Bottom Layer w5: v1(371,645.67) 371.06,645.73 v1(371.06,806.1) 378.82,806.1 v1@378.88,806.04 ; v3(545,1395) 595,1395 ccw(c595,1650) P1.4
PB10: P6.11 R4.2 T1.1 U4.21 | length 1319.1
  Top Layer w5: U4.21 749.21,851 ccw(c849.21,851) 849.21,751 1249,751 cw(c1249,750) P6.11
  Bottom Layer w5: R4.2 1106.07,520.61 T1.1 ccw(c1115.68,520.4) 1115.68,511 1245,511 ccw(c1245,558) 1292,558 1292,708 ccw(c1250,708) P6.11
PB13: P6.10 U4.26 U5.6 | length 619.1
  Top Layer w5: U4.26 1112.16,1011.42 cw(c1112.16,911.42) 1182.87,982.13 1193,972 cw(c1135.06,914.06) 1217,914.06 1217,896 ; U5.6 1190.68,869.68 ccw(c1190.68,896) 1217,896 ; P6.10 1226.21,873.79 cw(c1248.38,896) 1217,896
PB14: P6.9 U4.27 U5.2 | length 587.8
  Top Layer w5: U4.27 1127.48,1031.1 cw(c1127.48,931.1) 1198.19,1001.81 P6.9 ; v3(865,940) ccw(c885.32,940) 885.32,919.68 U5.2
  Bottom Layer w5: v3(865,940) v3(865,1031)
PB15: P6.8 U4.28 U5.5 | length 857.7
  Top Layer w5: U4.28 1248.1,1050.79 cw(c1248.1,1048.1) P6.8 cw(c1250,1003) 1297,1003 1297,844 cw(c1253,844) 1253,800 1145.47,800 cw(c1145.47,819.68) U5.5
PC13: D2.2 U4.2 | length 1183.6
  Top Layer w5: v3(474,1372) 474,1314.59 ccw(c574,1314.59) 503.29,1243.88 554.08,1193.1 ccw(c564.97,1203.99) 564.97,1188.58 U4.2 ; v1(813.98,1372.05) 973.43,1372.05 ccw(c973.43,1443.9) 1045.28,1443.9 1045.28,1520.8 cw(c1109.12,1520.8) 1063.98,1565.94 1064.46,1566.43 ccw(c1015.74,1615.16) 1084.65,1615.16 1084.65,1692.85 ccw(c1027.5,1692.85) D2.2
  Bottom Layer w5: v3(474,1372) v1(813.98,1372.05) v1(813.98,1372.05)
SPI2_FLASH_CS: U4.25 U5.1 | length 83.5
  Top Layer w5: U4.25 ccw(c854.92,991.73) 854.92,969.69 U5.1
TCK: P4.3 U4.37 | length 864
  Top Layer w5: U4.37 960.04,1232.87 ccw(c960.04,1332.87) 1060.04,1332.87 1060.04,1486.1 cw(c1189.09,1486.1) 1189.09,1615.16 1287.4,1615.16 cw(c1287.4,1552.56) 1350,1552.56 P4.3
TMS: P4.5 U4.34 | length 1059.4
  Top Layer w5: U4.34 941.52,1168.9 ccw(c941.52,1302.41) 1075.04,1302.41 1075.04,1485.63 cw(c1189.57,1485.63) 1189.57,1600.16 1273.86,1600.16 cw(c1273.86,1560.04) 1313.98,1560.04 1313.98,1386.02 ccw(c1350,1386.02) P4.5
UD+: P7.6 P7.8 U8.1 | length 357.2
  Top Layer w5: v3(672,321) v3(712,321) v3(780,321) 780,325.28 v3@780.51,325.79
  Bottom Layer w5: v3(672,321) 672,246.8 672.24,246.55 672,246.31 P7.8 ; P7.6 712,246.45 711.61,246.83 712,247.22 v3(712,321) ; U8.1@778.54,368.24 U8.1@778.54,373.03 ; U8.1@778.74,358.71 U8.1 cw(c774.46,372.83) 780.51,372.83 780,372.31 v3(780,321) ; U8.1@779.8,354.64 U8.1@779.8,368.24
UD-: P7.5 P7.7 U8.2 | length 259.9
  Bottom Layer w5: P7.7 691.93,323.93 cw(c706.58,323.93) 706.58,338.58 729.33,338.58 cw(c729.33,336.61) 731.3,336.61 ; P7.5 731.3,336.61 ; U8.2 ccw(c758.85,357.62) 731.3,357.62 731.3,338.58 731.3,336.61
USART2_RX: P5.14 U4.13 | length 834.8
  Top Layer w5: P5.14 ccw(c150,516) 216,516 216,627 cw(c294,627) 294,705 446.73,705 ccw(c446.73,850) 591.73,850 U4.13
USART2_TX: P5.13 U4.12 | length 732
  Top Layer w5: P5.13 ccw(c150,601) 201,601 201,627 cw(c294,627) 294,720 399.53,720 ccw(c399.53,850) 529.53,850 529.53,970.08 cw(c551.18,970.08) 551.18,991.73 U4.12
V3.3V: C5.2 P2.2 U3.1 | length 254.6
  Bottom Layer w12: U3.1 C5.2@467.58,1670.28
  Bottom Layer w20: C5.2@467.58,1670.28 C5.2 470.77,1673.47 cw(c541.48,1602.76) 541.48,1702.76 563.98,1702.76 ccw(c563.98,1796.38) 630.18,1730.18 P2.2
VCC: C1.2 C4.2 C22.2 F1.2 U1.4 U1.6 U3.4 U3.6 U8.7 | length 2585.2
  Top Layer w12: v1(584.65,629.92) ccw(c584.65,700.26) 634.38,650.52 v1(685.83,701.97)
  Bottom Layer w10: C4.2 ccw(c294.23,1672.18) 294.23,1670.28 U3.6
  Bottom Layer w12: 331.5,1575 ccw(c331.5,1585.24) 341.73,1585.24 U3.4 ; C1.2 ccw(c607.65,661.11) 614.17,661.11 U1.6 ; 616.14,526.57 644.67,555.1 ccw(c606.13,593.64) U8.7 ccw(c649.22,605.04) U8.7@665.35,605.04 ; U1.4 v1(685.83,701.97)
  Bottom Layer w25: C4.2 272.97,1672.18 ccw(c272.97,1634) 234.79,1634 ccw(c234.79,1632.48) 233.27,1632.48 233.27,1607.28 ccw(c265.55,1607.28) 265.55,1575 331.5,1575 cw(c331.5,1522.64) 383.86,1522.64 383.86,1410.52 cw(c283.86,1410.52) 354.57,1339.81 263.54,1248.78 ccw(c334.25,1178.07) 234.25,1178.07 234.25,399.61 ccw(c289.43,399.61) 289.43,344.43 F1.2 ccw(c500,410.37) 565.94,410.37 C22.2 566,454.72 601.5,454.72 616.14,469.37 616.14,526.57 585.63,557.09 585.63,628.36 612.26,655 C1.2
VCC_E: F1.1 P7.2 P7.11 | length 373.8
  Top Layer w15.75: v4@601,288 v4@602.74,286.26
  Top Layer w25: v4(607.28,290) v4(796,290)
  Bottom Layer w20: P7.2@796,246.32 P7.2
  Bottom Layer w25: F1.1@503.81,288.39 502.43,287 cw(c502.43,289.43) F1.1 500,290 v4(607.28,290) ; P7.11 607.28,274 ; P7.2@796,246.32 v4@796,287
VDD: B1.1 C2.2 C3.2 C6.2 C7.1 C13.1 C14.2 C15.2 C16.2 C17.2 D1.2 L1.1 P1.2 P3.2 P4.2 P5.2 P6.2 R1.2 R2.2 U1.1 U2.5 U4.1 U4.24 U4.36 U4.48 U5.3 U5.7 U5.8 U6.4 | length 6122.7
  Top Layer w5: v1(426.12,596.46) 426.12,574.86 ccw(c454.72,574.86) 454.72,546.26 cw(c454.72,521.65) 479.33,521.65 479.33,500.59 cw(c453.15,500.59) U2.5
  Top Layer w10: v1(563.12,1281.56) 563.12,1232.87 ; U4.1 cw(c567.13,1212.27) 563.12,1212.27 563.12,1232.87 ; U4.48 563.12,1232.87 ; U4.24 808.27,918.25 ccw(c827.76,918.25) v1(813.98,904.47) 819.47,898.97 ccw(c890.18,969.68) 890.18,869.68 U5.3 ; U4.36 v1@898.68,1208.27 ; U5.8 U5.7 1167.18,919.68 ccw(c1167.18,930.5) v1(1178,930.5)
  Top Layer w19.68: C13.1 313.29,1118.05 ccw(c313.29,1155.22) v1(339.57,1128.94)
  Top Layer w20: P5.2 cw(c197.83,1650) 197.83,1697.83 650,1697.83 ; P1.2 650,1697.83 ; D1.2 1027.5,1649.07 ccw(c1026.57,1649.07) v4(1026.57,1650) ccw(c978.74,1650) 978.74,1697.83 650,1697.83
  Bottom Layer w12: U1.1 C2.2@614.17,820.19
  Bottom Layer w19.68: 316,1129.92 337.19,1129.92 cw(c337.19,1126.56) v1(339.57,1128.94) ; v1@340.57,1126.89 391.43,1076.03 391.43,1074.53 399.09,1066.87 L1.1
  Bottom Layer w20: P3.2 P5.2 ; R1.2 316,858.27 ; v1(426.12,596.46) 432.03,596.46 ccw(c432.03,645.67) R2.2 481.24,856.03 ccw(c478.08,856.03) 480.32,858.27 ; C14.2 427.17,1281.56 ; C2.2@611.59,824.38 C2.2@614.17,820.19 ; C2.2 564.36,880.18 ; P1.2 650,1637 cw(c550,1637) 550,1537 527.17,1537 ccw(c527.17,1437) 427.17,1437 427.17,1281.56 ; v1(813.98,904.47) ccw(c766.44,904.47) 766.44,952 677.42,952 ccw(c677.42,854.51) 608.48,923.45 572.6,887.56 cw(c501.89,958.27) 564.36,880.18 ; v1(898.68,1208.66) C15.2 cw(c990.22,1260.83) 990.22,1352.36 1178,1352.36 ; B1.1 1022,581 ccw(c1022,667) 1108,667 1108,860.5 cw(c1178,860.5) v1(1178,930.5) 1178,1352.36 ; v4(1026.57,1650) 1179.13,1650 ; P4.2 P6.2 1179.13,1650 ; 316,858.27 480.32,858.27 ; 316,858.27 316,1129.92 316,1181.56 cw(c416,1181.56) 416,1281.56 427.17,1281.56 ; 480.32,858.27 501.89,858.27 ccw(c501.89,958.27) 564.36,880.18 ; 1178,1352.36 1178,1648.87 cw(c1179.13,1648.87) 1179.13,1650
pads on no net: P7.3 P7.4 P7.9 P7.10 P7.13 P7.14 P7.15 P7.16 U1.2 U1.3 U2.3 U2.4 U3.2 U3.3 U4.6 U6.1 U8.4 U8.5 U8.6 U8.11
copper on no net:
  other v2: 678.35,463.72 721.65,463.72 678.35,507.02 721.65,507.02

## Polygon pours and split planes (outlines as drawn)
GND on Top Layer "GND_L01_P000" (solid, remove dead copper, pour order 0): 0,1800 0,0 1400,0 1400,1800
GND on Bottom Layer "Bottom Layer-GND" (solid, remove dead copper, pour order 2): 0,1800 0,0 1400,0 1400,1800

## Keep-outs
Keep-Out Layer:
  lines w5: 267.72,378.94 523.62,378.94 523.62,575.79 ; 267.72,378.94 267.72,378.94 ; 267.72,378.94 267.72,574.8 268.7,575.79 329.72,575.79 329.72,556.1 295.28,556.1 295.28,398.62 497.05,398.62 497.05,556.1 462.6,556.1 462.6,575.79 523.62,575.79 ; 523.62,575.79 523.62,575.79
  lines w10: 0,50 ccw(c50,50) 50,0 1350,0 ccw(c1350,50) 1400,50 1400,1750 ccw(c1350,1750) 1350,1800 50,1800 ccw(c50,1750) 0,1750 0,50

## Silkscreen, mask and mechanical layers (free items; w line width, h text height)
Top Overlay:
  text "GND" at 11.81,1685.45 h56
  text "GND" at 115,1685.45 h56
  text "GND" at 511.81,1685.45 h56
  text "GND" at 1205.13,1685.45 h56
  text "GND" at 1312.01,1685.45 h56
  text "VDD" at 614.17,1685.04 h56
  text "TX" at 724.41,1685.04 h56
  text "RX" at 826.77,1685.04 h56
  text "GND" at 511.81,1588.41 h56
  text "SCL" at 720.47,1588.41 h56
  text "SDA" at 814.96,1588.41 h56
  text "VDD" at 11.81,1588 h56
  text "VDD" at 115,1588 h56
  text "VDD" at 614.17,1588 h56
  text "VDD" at 1205.13,1588 h56
  text "VDD" at 1312.01,1588 h56
  text "BOOT" at 11.81,1488.41 h56
  text "PA15" at 115,1488.41 h56
  text "TCK" at 1312.01,1488.36 h56
  text "PA12" at 1205.13,1488 h56
  text "GND" at 11.81,1386.24 h56
  text "PB3" at 115,1386.24 h56
  text "PA11" at 1205.13,1385.83 h56
  text "GND" at 1312.01,1386.24 h56
  text "GND" at 11.81,1283.88 h56
  text "PB4" at 115,1283.46 h56
  text "PA10" at 1205.13,1283.88 h56
  text "TMS" at 1312.01,1283.88 h56
  text "GND" at 11.81,1189.39 h56
  text "PB5" at 115,1188.41 h56
  text "PA9" at 1205.13,1186.06 h56
  text "RST" at 1312.01,1185.45 h56
  text "PB6" at 115,1088.41 h56
  text "GND" at 11.81,1087.03 h56
  text "PA8" at 1205.13,1083.48 h56
  text "GND" at 1312.01,1083.09 h56
  text "GND" at 11.81,988.6 h56
  text "GND" at 1312.01,988.6 h56
  text "PB7" at 115,987 h56
  text "PB15" at 1205.13,986.48 h56
  text "GND" at 11.81,886.24 h56
  text "PB8" at 115,886.24 h56
  text "PB14" at 1205.13,885.83 h56
  text "GND" at 1312.01,886.24 h56
  text "GND" at 11.81,783.88 h56
  text "PB9" at 115,783.46 h56
  text "PB13" at 1205.13,783.88 h56
  text "GND" at 1312.01,783.88 h56
  text "GND" at 11.81,682.5 h56
  text "PA0" at 115,682.5 h56
  text "PB10" at 1205.13,682.5 h56
  text "GND" at 1312.01,682.5 h56
  text "GND" at 11.81,585.06 h56
  text "PA1" at 115,584.65 h56
  text "PB2" at 1205.13,584.65 h56
  text "GND" at 1312.01,585.06 h56
  text "GND" at 11.81,484.67 h56
  text "PA2" at 115,484.25 h56
  text "PB1" at 1205.13,484.25 h56
  text "GND" at 1312.01,484.67 h56
  text "GND" at 11.81,384.27 h56
  text "PA3" at 115,384.27 h56
  text "PB0" at 1205.13,384.27 h56
  text "GND" at 1307.09,384.27 h56
  text "Tiny Bord" at 202.76,302.5 h110
  text "PA5" at 11.81,288.8 h56
  text "PA4" at 115,288.39 h56
  text "PA7" at 1205.13,288.39 h56
  text "PA6" at 1307.09,288.8 h56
